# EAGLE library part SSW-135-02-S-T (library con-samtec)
THROUGH-HOLE .025" SQ POST SOCKET Source: Samtec SSW.pdf
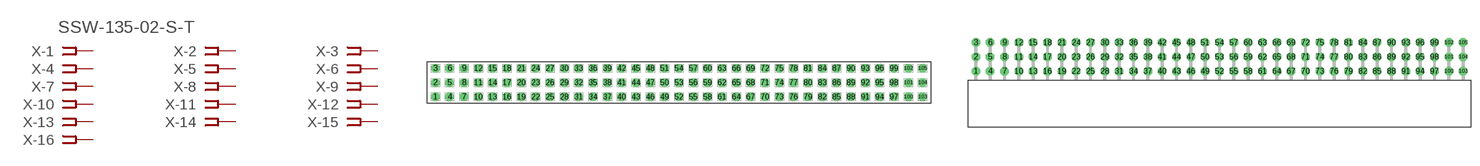
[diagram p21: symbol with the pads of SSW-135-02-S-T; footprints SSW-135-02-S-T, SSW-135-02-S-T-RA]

Designator prefix X; gates -1=FPINV -2=FPIN -3=FPIN -4=FPIN -5=FPIN -6=FPIN -7=FPIN -8=FPIN -9=FPIN -10=FPIN -11=FPIN -12=FPIN -13=FPIN -14=FPIN -15=FPIN -16=FPIN -17=FPIN -18=FPIN -19=FPIN -20=FPIN -21=FPIN -22=FPIN -23=FPIN -24=FPIN -25=FPIN -26=FPIN -27=FPIN -28=FPIN -29=FPIN -30=FPIN -31=FPIN -32=FPIN -33=FPIN -34=FPIN -35=FPIN -36=FPIN -37=FPIN -38=FPIN -39=FPIN -40=FPIN -41=FPIN -42=FPIN -43=FPIN -44=FPIN -45=FPIN -46=FPIN -47=FPIN -48=FPIN -49=FPIN -50=FPIN -51=FPIN -52=FPIN -53=FPIN -54=FPIN -55=FPIN -56=FPIN -57=FPIN -58=FPIN -59=FPIN -60=FPIN -61=FPIN -62=FPIN -63=FPIN -64=FPIN -65=FPIN -66=FPIN -67=FPIN -68=FPIN -69=FPIN -70=FPIN -71=FPIN -72=FPIN -73=FPIN -74=FPIN -75=FPIN -76=FPIN -77=FPIN -78=FPIN -79=FPIN -80=FPIN -81=FPIN -82=FPIN -83=FPIN -84=FPIN -85=FPIN -86=FPIN -87=FPIN -88=FPIN -89=FPIN -90=FPIN -91=FPIN -92=FPIN -93=FPIN -94=FPIN -95=FPIN -96=FPIN -97=FPIN -98=FPIN -99=FPIN -100=FPIN -101=FPIN -102=FPIN -103=FPIN -104=FPIN -105=FPIN

## SSW-135-02-S-T (MPN: SSW-135-02-S-T; OC_FARNELL: unknown; OC_NEWARK: 83P0778)  [SSW-135-02-S-T]
1  -1:1  pas
2  -2:1  pas
3  -3:1  pas
4  -4:1  pas
5  -5:1  pas
6  -6:1  pas
7  -7:1  pas
8  -8:1  pas
9  -9:1  pas
10  -10:1  pas
11  -11:1  pas
12  -12:1  pas
13  -13:1  pas
14  -14:1  pas
15  -15:1  pas
16  -16:1  pas
17  -17:1  pas
18  -18:1  pas
19  -19:1  pas
20  -20:1  pas
21  -21:1  pas
22  -22:1  pas
23  -23:1  pas
24  -24:1  pas
25  -25:1  pas
26  -26:1  pas
27  -27:1  pas
28  -28:1  pas
29  -29:1  pas
30  -30:1  pas
31  -31:1  pas
32  -32:1  pas
33  -33:1  pas
34  -34:1  pas
35  -35:1  pas
36  -36:1  pas
37  -37:1  pas
38  -38:1  pas
39  -39:1  pas
40  -40:1  pas
41  -41:1  pas
42  -42:1  pas
43  -43:1  pas
44  -44:1  pas
45  -45:1  pas
46  -46:1  pas
47  -47:1  pas
48  -48:1  pas
49  -49:1  pas
50  -50:1  pas
51  -51:1  pas
52  -52:1  pas
53  -53:1  pas
54  -54:1  pas
55  -55:1  pas
56  -56:1  pas
57  -57:1  pas
58  -58:1  pas
59  -59:1  pas
60  -60:1  pas
61  -61:1  pas
62  -62:1  pas
63  -63:1  pas
64  -64:1  pas
65  -65:1  pas
66  -66:1  pas
67  -67:1  pas
68  -68:1  pas
69  -69:1  pas
70  -70:1  pas
71  -71:1  pas
72  -72:1  pas
73  -73:1  pas
74  -74:1  pas
75  -75:1  pas
76  -76:1  pas
77  -77:1  pas
78  -78:1  pas
79  -79:1  pas
80  -80:1  pas
81  -81:1  pas
82  -82:1  pas
83  -83:1  pas
84  -84:1  pas
85  -85:1  pas
86  -86:1  pas
87  -87:1  pas
88  -88:1  pas
89  -89:1  pas
90  -90:1  pas
91  -91:1  pas
92  -92:1  pas
93  -93:1  pas
94  -94:1  pas
95  -95:1  pas
96  -96:1  pas
97  -97:1  pas
98  -98:1  pas
99  -99:1  pas
100  -100:1  pas
101  -101:1  pas
102  -102:1  pas
103  -103:1  pas
104  -104:1  pas
105  -105:1  pas

## SSW-135-02-S-TRA (MPN: SSW-135-02-S-T-RA; OC_FARNELL: unknown; OC_NEWARK: 83P0779)  [SSW-135-02-S-T-RA]
Pads as for SSW-135-02-S-T

## Footprint SSW-135-02-S-T (pad centres in mm)
THROUGH-HOLE .025" SQ POST SOCKET Source: Samtec SSW.pdf
drill 1 pad 1.5 octagon: 1 -43.18,-2.54; 2 -43.18,0; 3 -43.18,2.54; 4 -40.64,-2.54; 5 -40.64,0; 6 -40.64,2.54; 7 -38.1,-2.54; 8 -38.1,0; 9 -38.1,2.54; 10 -35.56,-2.54; 11 -35.56,0; 12 -35.56,2.54; 13 -33.02,-2.54; 14 -33.02,0; 15 -33.02,2.54; 16 -30.48,-2.54; 17 -30.48,0; 18 -30.48,2.54; 19 -27.94,-2.54; 20 -27.94,0; 21 -27.94,2.54; 22 -25.4,-2.54; 23 -25.4,0; 24 -25.4,2.54; 25 -22.86,-2.54; 26 -22.86,0; 27 -22.86,2.54; 28 -20.32,-2.54; 29 -20.32,0; 30 -20.32,2.54; 31 -17.78,-2.54; 32 -17.78,0; 33 -17.78,2.54; 34 -15.24,-2.54; 35 -15.24,0; 36 -15.24,2.54; 37 -12.7,-2.54; 38 -12.7,0; 39 -12.7,2.54; 40 -10.16,-2.54; 41 -10.16,0; 42 -10.16,2.54; 43 -7.62,-2.54; 44 -7.62,0; 45 -7.62,2.54; 46 -5.08,-2.54; 47 -5.08,0; 48 -5.08,2.54; 49 -2.54,-2.54; 50 -2.54,0; 51 -2.54,2.54; 52 0,-2.54; 53 0,0; 54 0,2.54; 55 2.54,-2.54; 56 2.54,0; 57 2.54,2.54; 58 5.08,-2.54; 59 5.08,0; 60 5.08,2.54; 61 7.62,-2.54; 62 7.62,0; 63 7.62,2.54; 64 10.16,-2.54; 65 10.16,0; 66 10.16,2.54; 67 12.7,-2.54; 68 12.7,0; 69 12.7,2.54; 70 15.24,-2.54; 71 15.24,0; 72 15.24,2.54; 73 17.78,-2.54; 74 17.78,0; 75 17.78,2.54; 76 20.32,-2.54; 77 20.32,0; 78 20.32,2.54; 79 22.86,-2.54; 80 22.86,0; 81 22.86,2.54; 82 25.4,-2.54; 83 25.4,0; 84 25.4,2.54; 85 27.94,-2.54; 86 27.94,0; 87 27.94,2.54; 88 30.48,-2.54; 89 30.48,0; 90 30.48,2.54; 91 33.02,-2.54; 92 33.02,0; 93 33.02,2.54; 94 35.56,-2.54; 95 35.56,0; 96 35.56,2.54; 97 38.1,-2.54; 98 38.1,0; 99 38.1,2.54; 100 40.64,-2.54; 101 40.64,0; 102 40.64,2.54; 103 43.18,-2.54; 104 43.18,0; 105 43.18,2.54

## Footprint SSW-135-02-S-T-RA (pad centres in mm)
THROUGH-HOLE .025" SQ POST SOCKET Source: Samtec SSW.pdf
drill 1 pad 1.5 octagon: 1 -43.18,1.524; 2 -43.18,4.064; 3 -43.18,6.604; 4 -40.64,1.524; 5 -40.64,4.064; 6 -40.64,6.604; 7 -38.1,1.524; 8 -38.1,4.064; 9 -38.1,6.604; 10 -35.56,1.524; 11 -35.56,4.064; 12 -35.56,6.604; 13 -33.02,1.524; 14 -33.02,4.064; 15 -33.02,6.604; 16 -30.48,1.524; 17 -30.48,4.064; 18 -30.48,6.604; 19 -27.94,1.524; 20 -27.94,4.064; 21 -27.94,6.604; 22 -25.4,1.524; 23 -25.4,4.064; 24 -25.4,6.604; 25 -22.86,1.524; 26 -22.86,4.064; 27 -22.86,6.604; 28 -20.32,1.524; 29 -20.32,4.064; 30 -20.32,6.604; 31 -17.78,1.524; 32 -17.78,4.064; 33 -17.78,6.604; 34 -15.24,1.524; 35 -15.24,4.064; 36 -15.24,6.604; 37 -12.7,1.524; 38 -12.7,4.064; 39 -12.7,6.604; 40 -10.16,1.524; 41 -10.16,4.064; 42 -10.16,6.604; 43 -7.62,1.524; 44 -7.62,4.064; 45 -7.62,6.604; 46 -5.08,1.524; 47 -5.08,4.064; 48 -5.08,6.604; 49 -2.54,1.524; 50 -2.54,4.064; 51 -2.54,6.604; 52 0,1.524; 53 0,4.064; 54 0,6.604; 55 2.54,1.524; 56 2.54,4.064; 57 2.54,6.604; 58 5.08,1.524; 59 5.08,4.064; 60 5.08,6.604; 61 7.62,1.524; 62 7.62,4.064; 63 7.62,6.604; 64 10.16,1.524; 65 10.16,4.064; 66 10.16,6.604; 67 12.7,1.524; 68 12.7,4.064; 69 12.7,6.604; 70 15.24,1.524; 71 15.24,4.064; 72 15.24,6.604; 73 17.78,1.524; 74 17.78,4.064; 75 17.78,6.604; 76 20.32,1.524; 77 20.32,4.064; 78 20.32,6.604; 79 22.86,1.524; 80 22.86,4.064; 81 22.86,6.604; 82 25.4,1.524; 83 25.4,4.064; 84 25.4,6.604; 85 27.94,1.524; 86 27.94,4.064; 87 27.94,6.604; 88 30.48,1.524; 89 30.48,4.064; 90 30.48,6.604; 91 33.02,1.524; 92 33.02,4.064; 93 33.02,6.604; 94 35.56,1.524; 95 35.56,4.064; 96 35.56,6.604; 97 38.1,1.524; 98 38.1,4.064; 99 38.1,6.604; 100 40.64,1.524; 101 40.64,4.064; 102 40.64,6.604; 103 43.18,1.524; 104 43.18,4.064; 105 43.18,6.604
